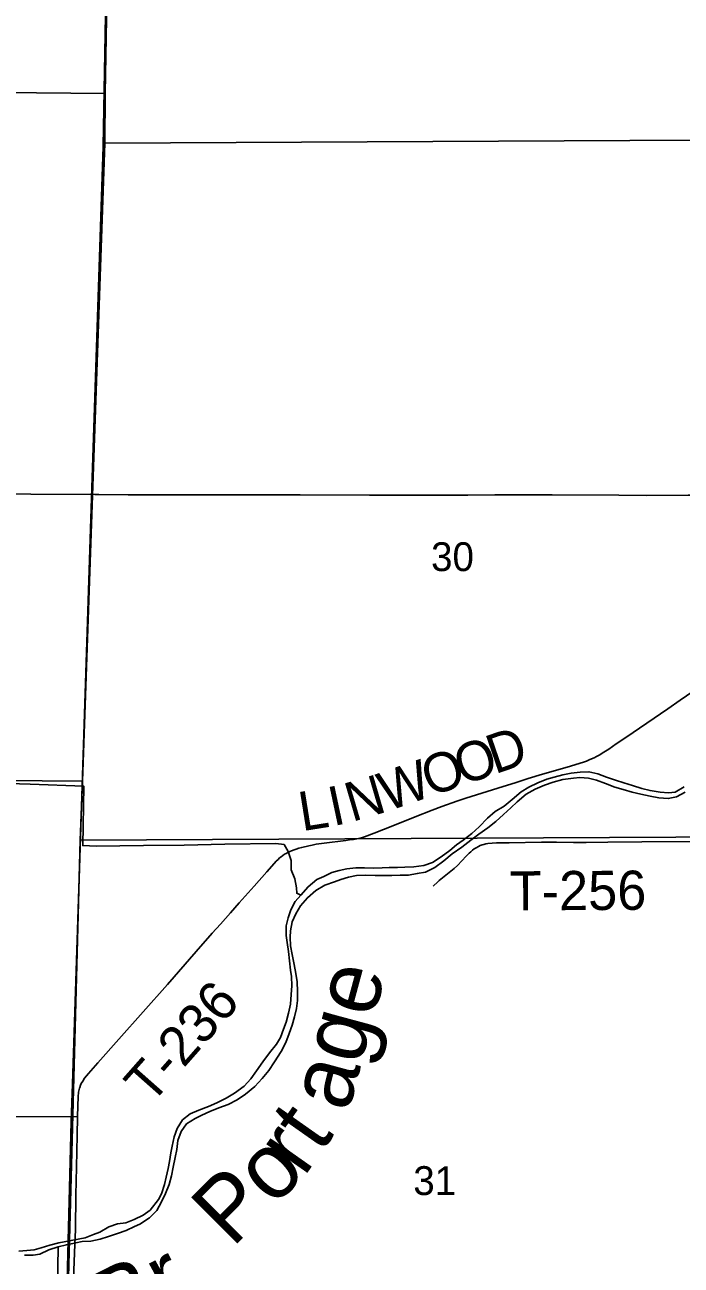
# Model space of a CAD drawing. Extents: x 1443599 to 1910620, y 1028088 to 1361369.
# Drawn here: x 1684107 to 1689140, y 1220494 to 1229998 of the extents above; entities that cross this region are included whole.
import ezdxf

# ---------------------------------------------------------------- set-up
doc = ezdxf.new("R2010")
doc.units = 0
for name, color, linetype in [('GM_X_County_Road', 7, 'Continuous'), ('GM_X_Major_River', 7, 'Continuous'), ('GM_X_Major_River_Text', 7, 'Continuous'), ('GM_X_Minor_River', 7, 'Continuous'), ('GM_X_Section', 7, 'Continuous'), ('GM_X_Section_Text', 7, 'Continuous'), ('GM_X_Township', 7, 'Continuous'), ('GM_X_Township_Road', 7, 'Continuous'), ('GM_X_Township_Road_Text', 7, 'Continuous'), ('GM_X_US_Route', 7, 'Continuous')]:
    doc.layers.add(name, color=color, linetype=linetype)

msp = doc.modelspace()

# ---------------------------------------------------------------- linework, layer by layer
at = {"layer": 'GM_X_County_Road'}
for points in [[(1684036.2, 1221633.3), (1684510.5, 1221630.2)], [(1684442, 1218794.9), (1684443.7, 1218875.1), (1684452.7, 1219254.3), (1684460.3, 1219550.4), (1684471.7, 1220044), (1684474.4, 1220142.7), (1684480.3, 1220373.1), (1684481.6, 1220422.5), (1684481.5, 1220438.9), (1684481.9, 1220455.2), (1684491.2, 1220652.4), (1684495, 1220767.6), (1684498.7, 1221031), (1684502.1, 1221244.9), (1684508.6, 1221491.6), (1684510.5, 1221630.2)]]:
    msp.add_lwpolyline(points, dxfattribs=at)
at = {"layer": 'GM_X_Major_River'}
for points in [[(1689162.7, 1224160.1), (1689093.8, 1224119.3), (1689043.5, 1224114.1), (1688979.4, 1224119.3), (1688901.4, 1224130.8), (1688837.4, 1224145.9), (1688767.6, 1224169.2), (1688699.8, 1224190.5), (1688635.9, 1224211.7), (1688568.1, 1224235), (1688500.4, 1224260.3), (1688432.4, 1224275.6), (1688364.1, 1224272.8), (1688295.8, 1224264), (1688231.3, 1224251.1), (1688164.8, 1224234.2), (1688110.4, 1224219.1), (1688041.6, 1224190.3), (1687970.8, 1224157.5), (1687913, 1224120.8), (1687844.7, 1224061.4), (1687781.6, 1224012.4), (1687714.6, 1223969.5), (1687655.5, 1223918.4), (1687590.1, 1223853.4), (1687534.6, 1223801.1), (1687467.8, 1223751.3), (1687417, 1223716.1), (1687366.1, 1223670.9)], [(1687658.2, 1223846.2), (1687719.3, 1223895.2), (1687778.4, 1223948.3), (1687834.3, 1223999.3), (1687882.5, 1224044.7), (1687951.8, 1224103.7), (1688020.7, 1224142.5), (1688091.4, 1224171.3), (1688158.1, 1224196.2), (1688231.8, 1224215.9), (1688314.6, 1224226.8), (1688363.4, 1224230.7), (1688429.9, 1224225.5), (1688491.4, 1224210.3), (1688559.2, 1224185), (1688631, 1224157.7), (1688694.9, 1224140.5), (1688764.7, 1224119.1), (1688830.6, 1224103.9), (1688902.6, 1224088.6), (1688968.6, 1224075.4), (1689040.7, 1224070.1), (1689105.2, 1224082.9), (1689170, 1224117.9)], [(1684103.7, 1220572.4), (1684169.9, 1220571.2), (1684222.2, 1220578.3), (1684291, 1220611.2), (1684361.7, 1220636), (1684426.2, 1220650.8), (1684496.7, 1220665.6), (1684547, 1220674.8), (1684613.3, 1220679.6), (1684683.8, 1220694.3), (1684748.3, 1220713.2), (1684817, 1220736.1), (1684883.6, 1220761), (1684948.4, 1220791.9), (1684989.2, 1220810), (1685062.4, 1220856.2), (1685119.1, 1220913.2), (1685154.5, 1220980.8), (1685185.7, 1221044.4), (1685213, 1221112.1), (1685232.3, 1221179.9), (1685243.5, 1221245.9), (1685258.9, 1221319.8), (1685272.1, 1221381.8), (1685281.3, 1221449.8), (1685304.7, 1221519.6), (1685347.8, 1221577), (1685412.8, 1221617.9), (1685463.4, 1221645.1), (1685526.1, 1221672.1), (1685594.8, 1221698.9), (1685665.5, 1221725.7), (1685734.4, 1221760.6), (1685799.4, 1221805.6), (1685870.7, 1221862.4), (1685928, 1221925.6), (1685977.2, 1221986.9), (1686020.6, 1222052.3), (1686072.2, 1222131.6), (1686109.5, 1222201.1), (1686132.8, 1222268.9), (1686158.1, 1222332.7), (1686175.3, 1222396.5), (1686190.5, 1222460.4), (1686197.6, 1222522.5), (1686198.9, 1222592.7), (1686194.1, 1222665), (1686185.3, 1222729.3), (1686172.5, 1222797.7), (1686155.8, 1222874.3), (1686145, 1222942.6), (1686142.1, 1223006.9), (1686145, 1223057), (1686156.3, 1223125), (1686185.5, 1223186.6), (1686220.7, 1223248.2), (1686274, 1223309.4), (1686339.2, 1223366.4), (1686407.2, 1223405.7), (1686480.5, 1223432.9), (1686529.3, 1223449.2), (1686587.7, 1223468.2), (1686651.4, 1223479.8), (1686720.6, 1223481.9), (1686793.9, 1223481.2), (1686865, 1223479.3), (1686921.2, 1223480.3), (1686985.5, 1223483.2), (1687047.7, 1223484.1), (1687116.1, 1223494.9), (1687180.5, 1223505.7), (1687251.4, 1223542.6), (1687320.5, 1223591.5), (1687383.7, 1223646.5), (1687456.8, 1223697.3), (1687526, 1223752.3), (1687589.1, 1223797.3), (1687658.2, 1223846.2)], [(1687366.1, 1223670.9), (1687299.9, 1223623.2), (1687233.4, 1223581.1), (1687165.4, 1223556.1), (1687088.9, 1223547.5), (1687020.7, 1223544.7), (1686964.4, 1223541.7), (1686900.2, 1223540.8), (1686846, 1223539.8), (1686783.8, 1223536.9), (1686711.6, 1223540.2), (1686645.3, 1223539.4), (1686575, 1223530.6), (1686516.5, 1223517.6), (1686462.1, 1223502.6), (1686399.4, 1223473.6), (1686346.8, 1223450.5), (1686279.5, 1223393.5), (1686224.2, 1223330.3), (1686180.7, 1223280.8), (1686146.8, 1223217), (1686126.7, 1223155.6), (1686111.6, 1223095.7), (1686110.3, 1223021.5), (1686117.3, 1222967.2), (1686128.1, 1222898.8), (1686136.9, 1222826.5), (1686143.6, 1222756.1), (1686150.7, 1222705.9), (1686153.5, 1222635.6), (1686148.2, 1222567.5), (1686142.9, 1222495.4), (1686129.6, 1222425.4), (1686110.3, 1222357.6), (1686091.3, 1222301.8), (1686066.1, 1222240), (1686037.1, 1222188.4), (1685983.7, 1222121.2), (1685932.3, 1222051.9), (1685882.9, 1221982.6), (1685839.6, 1221921.2), (1685787.8, 1221867.4), (1685715.3, 1221813.1), (1685650.4, 1221774.1), (1685579.5, 1221739.3), (1685514.8, 1221710.4), (1685440, 1221681.6), (1685375.5, 1221653.5), (1685316.3, 1221607.6), (1685275, 1221542.2), (1685251.7, 1221478.4), (1685236.4, 1221406.5), (1685227.4, 1221354.5), (1685216.2, 1221288.5), (1685207.2, 1221236.5), (1685190, 1221168.6), (1685178.9, 1221112.7), (1685155.9, 1221042.1), (1685132.9, 1220997.3), (1685069, 1220916.1), (1685014.1, 1220877), (1684945.3, 1220844.1), (1684880.7, 1220819.2), (1684818.3, 1220810.3), (1684751.7, 1220789.4), (1684682.8, 1220748.5), (1684632.3, 1220729.4), (1684568.6, 1220704.7), (1684368.2, 1220665.9), (1684297.7, 1220647.1), (1684231.1, 1220626.3), (1684178.6, 1220611.2), (1684122.4, 1220606.2), (1684060.1, 1220601.3)]]:
    msp.add_lwpolyline(points, dxfattribs=at)
at = {"layer": 'GM_X_Minor_River'}
for points in [[(1686224.2, 1223330.3), (1686192.4, 1223344.9), (1686191.1, 1223385.1), (1686176.3, 1223453.6), (1686149.5, 1223524.2), (1686150.1, 1223562.3), (1686148.7, 1223594.5), (1686125.9, 1223665.1), (1686094.8, 1223717.8), (1686032.7, 1223724.9), (1685639.3, 1223719.9), (1685328.2, 1223713.5), (1685017.1, 1223711), (1684653.8, 1223705.5), (1684551.6, 1223709.4), (1684559.8, 1224164.5), (1684148.7, 1224179.9), (1683651.4, 1224194.9)], [(1684361.7, 1220636), (1684343, 1219375.5), (1684330.1, 1218683.8), (1684296.4, 1217519.2), (1684278.6, 1216460.6), (1684251.6, 1215336.1), (1684221, 1214129.4), (1684199.2, 1213393.8)]]:
    msp.add_lwpolyline(points, dxfattribs=at)
at = {"layer": 'GM_X_Section'}
for points in [[(1679589.1, 1234842.6), (1684813, 1234803.1), (1684809.7, 1234352.9), (1684722.7, 1229472.7), (1679465, 1229524.3)], [(1684809.7, 1234352.9), (1690384.8, 1234393.3), (1690253.1, 1229119.8), (1684720.3, 1229090.6), (1684722.7, 1229472.7)], [(1679465, 1229524.3), (1684722.7, 1229472.7), (1684720.3, 1229090.6), (1684549, 1224204.3), (1679269.2, 1224246.2)], [(1690253.1, 1229119.8), (1690114.5, 1223778.9), (1684531.7, 1223752.3), (1684549, 1224204.3), (1684720.3, 1229090.6)], [(1679269.2, 1224246.2), (1684549, 1224204.3), (1684531.7, 1223752.3), (1684399.4, 1218775.6), (1679172.9, 1218926.9), (1679064.9, 1218932.2)], [(1684531.7, 1223752.3), (1690114.5, 1223778.9), (1689980.8, 1218518), (1684399.4, 1218775.6)]]:
    msp.add_lwpolyline(points, close=True, dxfattribs=at)
at = {"layer": 'GM_X_Township'}
for points in [[(1695360, 1218493.5), (1693450.7, 1218507.8), (1690109.2, 1218505.4), (1689981.8, 1218508.6), (1687448.3, 1218622.3), (1684389.9, 1218757.9), (1684463.4, 1221594.1), (1684471.3, 1221884.9), (1684620.7, 1226450.3), (1684707.1, 1229065.5), (1684756.5, 1231793.4), (1684762.1, 1232099), (1684807.3, 1234335.8), (1689711.4, 1234365.7), (1693554.1, 1234401), (1695686.2, 1234411.7)], [(1684756.5, 1231793.4), (1684707.1, 1229065.5), (1684620.7, 1226450.3), (1684471.3, 1221884.9), (1684463.4, 1221594.1), (1684389.9, 1218757.9), (1681774.9, 1218820.2), (1681020.1, 1218838.2), (1679176.9, 1218895.4), (1679066.2, 1218898.8), (1673902.1, 1219025.6), (1673809.8, 1219027.9), (1668556.1, 1219132.4)]]:
    msp.add_lwpolyline(points, dxfattribs=at)
at = {"layer": 'GM_X_Township_Road'}
for points in [[(1684526.6, 1221851.6), (1684527.8, 1221856.3), (1684534.2, 1221874.6), (1684539.8, 1221886.6), (1684550.5, 1221905.1), (1684565.4, 1221926.7), (1684594.3, 1221962.5), (1684665.6, 1222043.9), (1684827.4, 1222225.2), (1685200.2, 1222644.7), (1685420.5, 1222896.8), (1685543.7, 1223037.5), (1685607.1, 1223108.5), (1685683.1, 1223194.6), (1685750.4, 1223270.8), (1685864.2, 1223398.1), (1685961.9, 1223508.9), (1686018.4, 1223572.8), (1686034.3, 1223589.8), (1686048.3, 1223603.3), (1686060.7, 1223614.9), (1686072.6, 1223624.6), (1686084.6, 1223633.5), (1686097.2, 1223642.5), (1686109.8, 1223649.7), (1686123, 1223656.1), (1686137.9, 1223663.5), (1686152.9, 1223670.1), (1686170.9, 1223676.7), (1686186.7, 1223682.2), (1686209.2, 1223689.3), (1686230.8, 1223695.3), (1686285, 1223708.5), (1686311, 1223713.9), (1686339.7, 1223719.4), (1686401.3, 1223729.3), (1686567.4, 1223748.7), (1686597.3, 1223752.9), (1686626.7, 1223757.1), (1686653.6, 1223762), (1686677, 1223767.3), (1686695, 1223772.2), (1686712.3, 1223777.5), (1686786.6, 1223803.9), (1686858.2, 1223832.8), (1687006.1, 1223892.2), (1687100.7, 1223929.6), (1687231, 1223982), (1687304.7, 1224009), (1687420.2, 1224049.7), (1687488.7, 1224072.7), (1687610.9, 1224110.6), (1687733.2, 1224148.2), (1687874, 1224192.8), (1687967.6, 1224223.3), (1688077.2, 1224257.7), (1688175, 1224285.9), (1688291.9, 1224318.7), (1688364.2, 1224340.5), (1688389.9, 1224349.1), (1688413.8, 1224357.6), (1688433.6, 1224365.3), (1688453.3, 1224373.6), (1688472.6, 1224382.7), (1688491.6, 1224392.4), (1688515.1, 1224405.4), (1688534.3, 1224416.9), (1688584, 1224448.8), (1688640.6, 1224488.2), (1688714.2, 1224537.6), (1689036.6, 1224758), (1689131.3, 1224822.6), (1689230.3, 1224890.2)], [(1687239.1, 1223398.8), (1687273, 1223431.1), (1687285.1, 1223442.1), (1687297.6, 1223452.7), (1687349.2, 1223493.1), (1687400.3, 1223534.4), (1687424.4, 1223556.5), (1687459, 1223591.5), (1687492.1, 1223627.9), (1687514.9, 1223651.5), (1687527, 1223662.5), (1687538.7, 1223673.3), (1687552.6, 1223683.8), (1687567.3, 1223693.3), (1687584.7, 1223702.9), (1687597.7, 1223709.9), (1687612.5, 1223715.1), (1687627.2, 1223718.5), (1687642.1, 1223722.9), (1687658.2, 1223725.8), (1687691.5, 1223729), (1687723.6, 1223729.9), (1687756.3, 1223731.2), (1687821.9, 1223731.6), (1688067.9, 1223734.5), (1688182.7, 1223734.6), (1688313.9, 1223733.8), (1688412.3, 1223734.2), (1688576.3, 1223735.7), (1688838.7, 1223738), (1689248.8, 1223740.6)], [(1684510.5, 1221630.2), (1684512.1, 1221714.6), (1684515.6, 1221783.4), (1684519.6, 1221819.3), (1684524.1, 1221841.8), (1684526.6, 1221851.6)]]:
    msp.add_lwpolyline(points, dxfattribs=at)
at = {"layer": 'GM_X_US_Route'}
msp.add_lwpolyline([(1683742.9, 1226405.2), (1684153.3, 1226402), (1684642.4, 1226399.9), (1684674.4, 1226399.6), (1684898.4, 1226398), (1685249.7, 1226398.1), (1685722.4, 1226396.8), (1686218.1, 1226397.4), (1686749.9, 1226395.4), (1687147.1, 1226395.6), (1687504.9, 1226394.7), (1687711.7, 1226396.6), (1687862.7, 1226396.9), (1688151.6, 1226396.5), (1688660.5, 1226394), (1688873.8, 1226393), (1689192.2, 1226393.8), (1689395.7, 1226395.6), (1689635.4, 1226394.7), (1690199.2, 1226396.8)], dxfattribs=at)

# ---------------------------------------------------------------- texts
at = {"layer": 'GM_X_Major_River_Text'}
for s, height, rotation, p in [('age', 500.32, 74.90407, (1686587.2, 1221660.2)), ('rt', 500.31, 54.90503, (1686246.8, 1221163.7)), ('Po', 500.3, 44.90493, (1685696.7, 1220622)), ('Br.', 500.28, 27.07867, (1684796.1, 1219941.7))]:
    msp.add_text(s, height=height, rotation=rotation, dxfattribs=at).set_placement(p)
at = {"layer": 'GM_X_Section_Text'}
for s, p in [('30', (1687222, 1225812.6)), ('31', (1687085.6, 1221032))]:
    msp.add_text(s, height=221, rotation=0.00001, dxfattribs=at).set_placement(p)
at = {"layer": 'GM_X_Township_Road_Text'}
for s, rotation, p in [('D', 19.05125, (1687710.8, 1224254.5)), ('O', 19.05496, (1687461.2, 1224168.3)), ('O', 19.05125, (1687211.7, 1224082.1)), ('W', 19.06628, (1686883.2, 1223968.5)), ('N', 16.34639, (1686615, 1223889.5)), ('L', 9.07199, (1686232.4, 1223819.3)), ('I', 12.02378, (1686470.6, 1223857.8)), ('T-256', 0.28194, (1687825.2, 1223212.6)), ('T-236', 48.57666, (1685073.6, 1221716.8))]:
    msp.add_text(s, height=300, rotation=rotation, dxfattribs=at).set_placement(p)

doc.saveas('drawing.dxf')
